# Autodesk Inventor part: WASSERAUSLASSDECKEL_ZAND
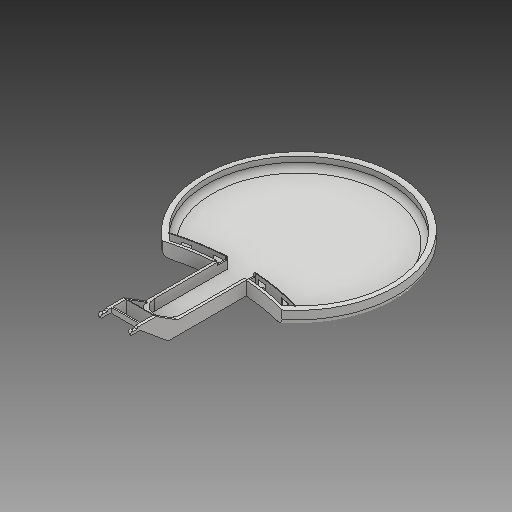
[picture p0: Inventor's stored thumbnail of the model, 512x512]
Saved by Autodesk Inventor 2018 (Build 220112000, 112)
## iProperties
Created: 2019-01
Part Number: WASSERAUSLASSDECKEL_ZAND
Material: Polypropylene (PP)
Document SubType Name: Modeling
Designer: zand
Density: 0.902188 g/cm^3
Appearance: Vorgabe
Mass: 43.1028 g
Surface Area: 439.124 cm^2
Volume: 47.7759 cm^3
Author: zand
Revision Number: 31LAST_VERSION
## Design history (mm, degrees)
feature "Basis1"
node "Volumenkörper1"
